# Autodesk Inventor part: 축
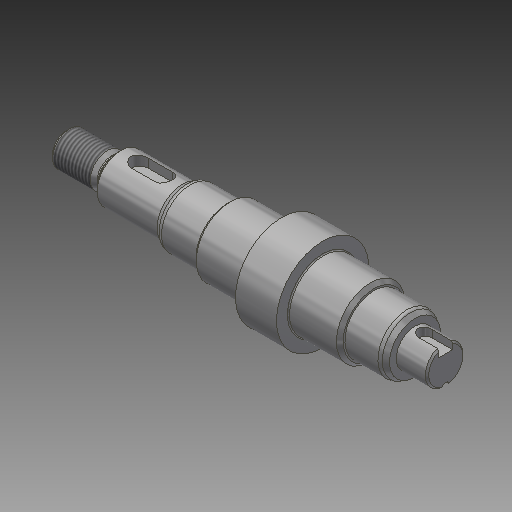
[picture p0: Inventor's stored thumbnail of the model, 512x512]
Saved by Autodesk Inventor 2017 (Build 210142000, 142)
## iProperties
Created: 2019-09
Part Number: 축
Material: 강철, 연강
Document SubType Name: Modeling
Designer: mduedu
Density: 7.86 g/cm^3
Mass: 210.278 g
Surface Area: 69.4769 cm^2
Volume: 26.7529 cm^3
Appearance: 강철
Author: mduedu
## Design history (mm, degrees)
sketch "스케치1"
  geometry: L1 (0, 0)-(15, 0); L2 (15, 0)-(15, 5); L3 (15, 5)-(0, 5); L4 (0, 5)-(0, 0); L5 (15, 0)-(34, 0); L6 (34, 0)-(34, 7); L7 (34, 7)-(15, 7); L8 (15, 7)-(15, 0); L9 (34, 0)-(47, 0); L10 (47, 0)-(47, 8.5); L11 (47, 8.5)-(34, 8.5); L12 (34, 8.5)-(34, 0); L13 (47, 0)-(63, 0); L14 (63, 0)-(63, 10); L15 (63, 10)-(47, 10); L16 (47, 10)-(47, 0); L17 (63, 0)-(75, 0); L18 (75, 0)-(75, 13.5); L19 (75, 13.5)-(63, 13.5); L20 (63, 13.5)-(63, 0); L21 (75, 0)-(90, 0); L22 (90, 0)-(90, 10); L23 (90, 10)-(75, 10); L24 (75, 10)-(75, 0); L25 (90, 0)-(102, 0); L26 (102, 0)-(102, 8.5); L27 (102, 8.5)-(90, 8.5); L28 (90, 8.5)-(90, 0); L29 (102, 0)-(111, 0); L30 (111, 0)-(111, 5.5); L31 (111, 5.5)-(102, 5.5); L32 (102, 5.5)-(102, 0)
  constraints: 64 end point, 16 parallel, 8 horizontal, 8 perpendicular
  dimensions: "d0" = 111 distance between parallel lines of L30 L4; "d2" = 15 distance of L2.end L3.end; "d3" = 19 distance of L6.end L7.end; "d4" = 12 distance of L18.end L19.end; "d5" = 15 distance of L22.end L23.end; "d6" = 12 distance of L26.end L27.end; "d7" = 9 distance of L30.end L31.end; "d8" = 16 distance of L14.end L15.end; "d9" = 10 diameter of L3 L1; "d10" = 14 diameter of L7 L5; "d11" = 17 diameter of L11 L9; "d12" = 20 diameter of L15 L13; "d13" = 27 diameter of L19 L17; "d14" = 20 diameter of L23 L21; "d15" = 17 diameter of L27 L25; "d16" = 11 diameter of L31 L29
revolve "회전1" sketch "스케치1" stored, may be unused: angle "d17" = 90 deg
sketch "스케치2"
  geometry: L1 (0, -5)-(0, 5) reference; L2 (0, 5)-(15, 5) reference; L3 (15, 5)-(15, 7) reference; L4 (15, 7)-(34, 7) reference; L5 (34, 7)-(34, 8.5) reference; L6 (34, 8.5)-(47, 8.5) reference; L7 (47, 8.5)-(47, 10) reference; L8 (47, 10)-(63, 10) reference; L9 (63, 10)-(63, 13.5) reference; L10 (63, 13.5)-(75, 13.5) reference; L11 (75, 13.5)-(75, 10) reference; L12 (75, 10)-(90, 10) reference; L13 (90, 10)-(90, 8.5) reference; L14 (90, 8.5)-(102, 8.5) reference; L15 (102, 8.5)-(102, 5.5) reference; L16 (102, 5.5)-(111, 5.5) reference; L17 (111, 5.5)-(111, -5.5) reference; L18 (111, -5.5)-(102, -5.5) reference; L19 (102, -5.5)-(102, -8.5) reference; L20 (102, -8.5)-(90, -8.5) reference; L21 (90, -8.5)-(90, -10) reference; L22 (90, -10)-(75, -10) reference; L23 (75, -10)-(75, -13.5) reference; L24 (75, -13.5)-(63, -13.5) reference; L25 (63, -13.5)-(63, -10) reference; L26 (63, -10)-(47, -10) reference; L27 (47, -10)-(47, -8.5) reference; L28 (47, -8.5)-(34, -8.5) reference; L29 (34, -8.5)-(34, -7) reference; L30 (34, -7)-(15, -7) reference; L31 (15, -7)-(15, -5) reference; L32 (15, -5)-(0, -5) reference; L33 (0, 0)-(111, 0); L34 (15, 5)-(12.014, 5); L35 (13.4, 4.2)-(15, 4.2); L36 (15, 4.2)-(15, 5); L37 (12.014, 5)-(13.4, 4.2)
  constraints: 10 end point, 1 horizontal, 1 midpoint, 1 parallel, 1 vertical
  dimensions: "d18" = 30 deg angle of L2 L37; "d19" = 8.4 diameter of L35 L33; "d21" = 2.986 distance from line of L34.end L36
revolve "회전2" sketch "스케치2" stored, may be unused: angle "d22" = 90 deg
fillet "모깎기1" dims "d23" = 0.6
feature "스레드1" dims "d24" = 10, "d25" = 0
chamfer "모따기1" distance "d26" = 1; stored, may be unused: second distance "d27" = 2, angle "d28" = 45 deg
chamfer "모따기2" distance "d29" = 1; stored, may be unused: second distance "d30" = 2, angle "d31" = 45 deg
chamfer "모따기3" distance "d32" = 1.819; stored, may be unused: second distance "d33" = 2, angle "d34" = 30 deg
fillet "모깎기2" dims "d35" = 2
chamfer "모따기4" distance "d36" = 1; stored, may be unused: second distance "d37" = 2, angle "d38" = 30 deg
fillet "모깎기3" dims "d39" = 0.3
chamfer "모따기5" distance "d40" = 1; stored, may be unused: second distance "d41" = 2, angle "d42" = 30 deg
chamfer "모따기6" distance "d43" = 1.819; stored, may be unused: second distance "d44" = 2, angle "d45" = 30 deg
chamfer "모따기7" distance "d46" = 0.5; stored, may be unused: second distance "d47" = 2, angle "d48" = 30 deg
fillet "모깎기4" dims "d49" = 2
node "작업 평면1"
sketch "스케치3" dims "d51" = 12
  geometry: L1 (3, -2.5)-(-4, -2.5); L2 (-4, -2.5)-(-4, 2.5); L3 (-4, 2.5)-(3, 2.5); L4 (3, 2.5)-(3, -2.5); L5 (-9.5, 7.45)-(-9.5, -7.45) reference; 3 further points
  constraints: 8 end point, 2 midpoint, 2 parallel, 2 vertical alignment, 1 horizontal, 1 horizontal alignment, 1 perpendicular, 4 other
  dimensions: "d50" = 3 dimension on L5; "d52" = 5 distance between parallel lines of L3 L1
extrude "돌출1" cut sketch "스케치3" distance "d53" = 3; taper "d54" = 0 deg
node "작업 평면3"
sketch "스케치4"
  geometry: L1 (-4.5, -5)-(-4.5, 5) reference; L2 (-4.5, -2)-(1.5, -2); L3 (1.5, -2)-(1.5, 2); L4 (1.5, 2)-(-4.5, 2); L5 (-4.5, 2)-(-4.5, -2); 3 further points
  constraints: 8 end point, 2 horizontal alignment, 2 midpoint, 2 parallel, 1 horizontal, 1 perpendicular, 1 point on line, 1 vertical alignment, 2 other
  dimensions: "d55" = 4 distance between parallel lines of L4 L2; "d57" = 8 dimension on L1
extrude "돌출2" cut sketch "스케치4" distance "d58" = 2.5; taper "d59" = 0 deg
sketch "스케치5"
  geometry: A1 r 5.5 centre (2, -3) between (0, 2.123) and (4, 2.123) reference; 2 further points
  constraints: 1 point on circle
hole "구멍1" sketch "스케치5" at (2, -8.5) diameter "d60" = 2.459; stored, may be unused: countersink angle "d64" = 90 deg, drill point angle "d66" = 118 deg; dims "d61" = 6, "d62" = 4, "d63" = 2, "d65" = 5
node "솔리드1"
node "절단 모서리 투영1"
